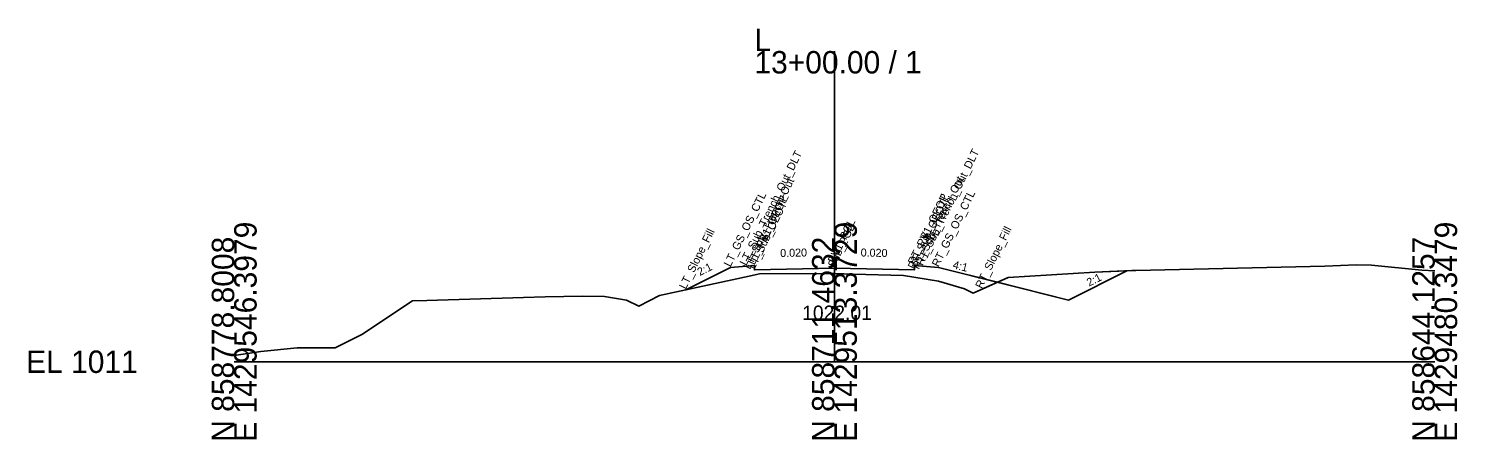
# Model space of a CAD drawing. Extents: x -26 to 176, y -10 to 13058.
# Drawn here: x -25.7 to 152.8, y 2990.3 to 3041.6 of the extents above; entities that cross this region are included whole.
import ezdxf

# ---------------------------------------------------------------- set-up
doc = ezdxf.new("R2010")
doc.units = 0
for name, color, linetype in [('Default', 7, 'Continuous'), ('Exist Cross Section Cell', 7, 'Continuous'), ('Exist XS Center Line Elevation Label', 7, 'Continuous'), ('Exist XS Ground Line', 7, 'Continuous'), ('Old_Level_50', 7, 'Continuous'), ('Prop CMT Pvmt Course 1', 7, 'Continuous'), ('Prop CMT Pvmt Surface Shoulder', 7, 'Continuous'), ('Prop CMT Shld Paved Course 1', 7, 'Continuous'), ('Prop CMT Slope Grass', 7, 'Continuous'), ('Prop CMT Subgrade Earthwork', 7, 'Continuous'), ('Prop XS Dump Level', 7, 'Continuous'), ('Prop XS SE Text', 7, 'Continuous'), ('Prop XS Side Slope Text', 7, 'Continuous')]:
    doc.layers.add(name, color=color, linetype=linetype)

msp = doc.modelspace()

# ---------------------------------------------------------------- linework, layer by layer
at = {"layer": 'Exist Cross Section Cell'}
for p, q in [((75, 3000), (75, 3038.78)), ((0, 3000), (75, 3000)), ((75, 3000), (150, 3000))]:
    msp.add_line(p, q, dxfattribs=at)
at = {"layer": 'Exist XS Ground Line'}
msp.add_lwpolyline([(0, 3000.79), (3.33, 3001.29), (7.86, 3001.73), (9.04, 3001.75), (12.6, 3001.73), (15.96, 3003.38), (22.29, 3007.62), (24.06, 3007.64), (36.14, 3008), (38.85, 3008.12), (43.5, 3008.2), (46.25, 3008.14), (49.01, 3007.67), (50.56, 3006.95), (53.14, 3008.26), (64.33, 3010.69), (65.28, 3010.9), (65.63, 3010.97), (74.66, 3011.02), (75, 3011.01), (77.34, 3010.94), (83.63, 3010.75), (87.99, 3010.07), (91.26, 3009.09), (92.35, 3008.57), (96.72, 3010.5), (107.55, 3011.17), (112.16, 3011.38), (112.65, 3011.38), (136.29, 3011.93), (140.2, 3012.1), (142.11, 3012.04), (148.38, 3011.42), (150, 3011.33)], dxfattribs=at)
at = {"layer": 'Old_Level_50'}
for points in [[(56.42, 3008.97), (64.33, 3010.69), (65.28, 3010.9), (65.63, 3010.97), (74.66, 3011.02), (75, 3011.01), (77.34, 3010.94), (83.63, 3010.75), (87.99, 3010.07), (91.26, 3009.09), (92.35, 3008.57), (95.39, 3009.92), (88, 3011.76), (85, 3012), (85, 3011.46), (75, 3011.66), (65, 3011.46), (65, 3012), (62, 3011.76)], [(62, 3011.76), (56.42, 3008.97), (64.33, 3010.69), (65.28, 3010.9), (65.63, 3010.97), (74.66, 3011.02), (75, 3011.01), (77.34, 3010.94), (83.63, 3010.75), (87.99, 3010.07), (91.26, 3009.09), (92.35, 3008.57), (95.39, 3009.92), (88, 3011.76), (85, 3012), (85, 3011.46), (75, 3011.66), (65, 3011.46), (65, 3012)], [(62, 3011.76), (56.42, 3008.97), (64.33, 3010.69), (65.28, 3010.9), (65.63, 3010.97), (74.66, 3011.02), (75, 3011.01), (77.34, 3010.94), (83.63, 3010.75), (87.99, 3010.07), (91.26, 3009.09), (92.35, 3008.57), (95.39, 3009.92), (88, 3011.76), (85, 3012), (85, 3011.46), (75, 3011.66), (65, 3011.46), (65, 3012)], [(104.25, 3007.7), (111.55, 3011.35), (107.55, 3011.17), (96.72, 3010.5), (95.39, 3009.92)], [(104.25, 3007.7), (111.55, 3011.35), (107.55, 3011.17), (96.72, 3010.5), (95.39, 3009.92)], [(104.25, 3007.7), (111.55, 3011.35), (107.55, 3011.17), (96.72, 3010.5), (95.39, 3009.92)]]:
    msp.add_lwpolyline(points, close=True, dxfattribs=at)
at = {"layer": 'Prop CMT Pvmt Course 1'}
for points in [[(65, 3012), (65, 3011.46)], [(85, 3012), (85, 3011.46)], [(65, 3011.46), (75, 3011.66)], [(85, 3011.46), (75, 3011.66)]]:
    msp.add_lwpolyline(points, dxfattribs=at)
at = {"layer": 'Prop CMT Pvmt Surface Shoulder'}
for points in [[(65, 3012), (65, 3012)], [(85, 3012), (85, 3012)]]:
    msp.add_lwpolyline(points, dxfattribs=at)
at = {"layer": 'Prop CMT Shld Paved Course 1'}
for points in [[(65, 3012), (65, 3012)], [(65, 3011.46), (65, 3012)], [(85, 3012), (85, 3012)], [(85, 3011.46), (85, 3012)]]:
    msp.add_lwpolyline(points, dxfattribs=at)
at = {"layer": 'Prop CMT Slope Grass'}
for p, q in [((88, 3011.76), (104.25, 3007.7)), ((104.25, 3007.7), (111.55, 3011.35))]:
    msp.add_line(p, q, dxfattribs=at)
for points in [[(65, 3012), (62, 3011.76), (56.42, 3008.97)], [(85, 3012), (88, 3011.76)]]:
    msp.add_lwpolyline(points, dxfattribs=at)
at = {"layer": 'Prop CMT Subgrade Earthwork'}
for points in [[(75, 3011.66), (65, 3011.46)], [(75, 3011.66), (85, 3011.46)]]:
    msp.add_lwpolyline(points, dxfattribs=at)

# ---------------------------------------------------------------- texts
at = {"layer": 'Default'}
msp.add_text('-', height=0.0001, dxfattribs=at).set_placement((0, 3000))
at = {"layer": 'Exist Cross Section Cell'}
for s, p in [('L', (65, 3038.78)), ('13+00.00 / 1', (65, 3035.98)), ('EL 1011', (-26, 2998.6))]:
    msp.add_text(s, height=2.8, dxfattribs=at).set_placement(p)
for s, p in [('E 1429546.3979', (2.8, 2990)), ('E 1429513.3729', (77.8, 2990)), ('E 1429480.3479', (152.8, 2990)), ('N 858778.8008', (0, 2990)), ('N 858711.4632', (75, 2990)), ('N 858644.1257', (150, 2990))]:
    msp.add_text(s, height=2.8, rotation=90, dxfattribs=at).set_placement(p)
at = {"layer": 'Exist XS Center Line Elevation Label'}
msp.add_text('1022.01', height=1.8, dxfattribs=at).set_placement((70.97, 3005.21))
msp.add_text('1022.01', height=1.8, dxfattribs=at).set_placement((70.97, 3005.21))
msp.add_text('1022.01', height=1.8, dxfattribs=at).set_placement((70.97, 3005.21))
at = {"layer": 'Prop XS Dump Level'}
for s, p in [('LT_Sub_Trench_Out_DLT', (63.98, 3011.92)), ('RT_Sub_Trench_Out_DLT', (86.02, 3011.92)), ('RT_Sub_Trench_Out_DLT', (86.02, 3011.92)), ('LT_Sub_Trench_Out', (64.45, 3011.45)), ('RT_Sub_Trench_Out', (85.55, 3011.45)), ('RT_Sub_Trench_Out', (85.55, 3011.45)), ('LT_GS_OS_CTL', (62, 3011.76)), ('LT_GS_OS_CTL', (62, 3011.76)), ('LT_PV1_OEOT', (65, 3012)), ('RT_PV1_OEOT', (85, 3012)), ('RT_PV1_OEOT', (85, 3012)), ('RT_PS1_OEOP', (85, 3012)), ('RT_PS1_OEOP', (85, 3012)), ('RT_GS_OS_CTL', (88, 3011.76)), ('RT_GS_OS_CTL', (88, 3011.76)), ('LT_PS1_OEOP', (65, 3012)), ('LT_Sub_OEOT', (65, 3011.46)), ('RT_Sub_OEOT', (85, 3011.46)), ('RT_Sub_OEOT', (85, 3011.46)), ('PV1_PGL', (75, 3012.2)), ('LT_Slope_Fill', (56.42, 3008.97)), ('LT_Slope_Fill', (56.42, 3008.97)), ('Sub_PGL', (75, 3011.66)), ('RT_Slope_Fill', (93.43, 3009.05))]:
    msp.add_text(s, height=1, rotation=63.5833, dxfattribs=at).set_placement(p)
at = {"layer": 'Prop XS SE Text'}
for rotation, p in [(1.1458, (68.23, 3013.07)), (358.8542, (78.27, 3013.14))]:
    msp.add_text('0.020', height=1, rotation=rotation, dxfattribs=at).set_placement(p)
at = {"layer": 'Prop XS Side Slope Text'}
for s, rotation, p in [('2:1', 26.5651, (58.17, 3010.68)), ('4:1', 345.9638, (89.72, 3011.67)), ('2:1', 26.5651, (106.82, 3009.37))]:
    msp.add_text(s, height=1, rotation=rotation, dxfattribs=at).set_placement(p)

doc.saveas('drawing.dxf')
